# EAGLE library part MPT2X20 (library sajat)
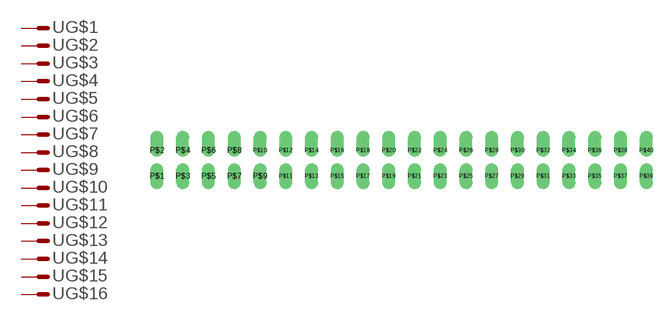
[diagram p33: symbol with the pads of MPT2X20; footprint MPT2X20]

Designator prefix -; gates G$1=M G$2=M G$3=M G$4=M G$5=M G$6=M G$7=M G$8=M G$9=M G$10=M G$11=M G$12=M G$13=M G$14=M G$15=M G$16=M G$17=M G$18=M G$19=M G$20=M G$21=M G$22=M G$23=M G$24=M G$25=M G$26=M G$27=M G$28=M G$29=M G$30=M G$31=M G$32=M G$33=M G$34=M G$35=M G$36=M G$37=M G$38=M G$39=M G$40=M

## MPT2X20  [MPT2X20]
P$1  G$1:M  pas
P$2  G$2:M  pas
P$3  G$3:M  pas
P$4  G$4:M  pas
P$5  G$5:M  pas
P$6  G$6:M  pas
P$7  G$7:M  pas
P$8  G$8:M  pas
P$9  G$9:M  pas
P$10  G$10:M  pas
P$11  G$11:M  pas
P$12  G$12:M  pas
P$13  G$13:M  pas
P$14  G$14:M  pas
P$15  G$15:M  pas
P$16  G$16:M  pas
P$17  G$17:M  pas
P$18  G$18:M  pas
P$19  G$19:M  pas
P$20  G$20:M  pas
P$21  G$21:M  pas
P$22  G$22:M  pas
P$23  G$23:M  pas
P$24  G$24:M  pas
P$25  G$25:M  pas
P$26  G$26:M  pas
P$27  G$27:M  pas
P$28  G$28:M  pas
P$29  G$29:M  pas
P$30  G$30:M  pas
P$31  G$31:M  pas
P$32  G$32:M  pas
P$33  G$33:M  pas
P$34  G$34:M  pas
P$35  G$35:M  pas
P$36  G$36:M  pas
P$37  G$37:M  pas
P$38  G$38:M  pas
P$39  G$39:M  pas
P$40  G$40:M  pas

## Footprint MPT2X20 (pad centres in mm)
drill 0.5 pad 1.27 long: P$1 -24.13,-1.27; P$3 -21.59,-1.27; P$5 -19.05,-1.27; P$7 -16.51,-1.27; P$9 -13.97,-1.27; P$11 -11.43,-1.27; P$13 -8.89,-1.27; P$15 -6.35,-1.27; P$17 -3.81,-1.27; P$19 -1.27,-1.27; P$21 1.27,-1.27; P$23 3.81,-1.27; P$25 6.35,-1.27; P$27 8.89,-1.27; P$29 11.43,-1.27; P$31 13.97,-1.27; P$33 16.51,-1.27; P$35 19.05,-1.27; P$37 21.59,-1.27; P$39 24.13,-1.27
drill 0.5 pad 1.27 offset: P$2 -24.13,1.27; P$4 -21.59,1.27; P$6 -19.05,1.27; P$8 -16.51,1.27; P$10 -13.97,1.27; P$12 -11.43,1.27; P$14 -8.89,1.27; P$16 -6.35,1.27; P$18 -3.81,1.27; P$20 -1.27,1.27; P$22 1.27,1.27; P$24 3.81,1.27; P$26 6.35,1.27; P$28 8.89,1.27; P$30 11.43,1.27; P$32 13.97,1.27; P$34 16.51,1.27; P$36 19.05,1.27; P$38 21.59,1.27; P$40 24.13,1.27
